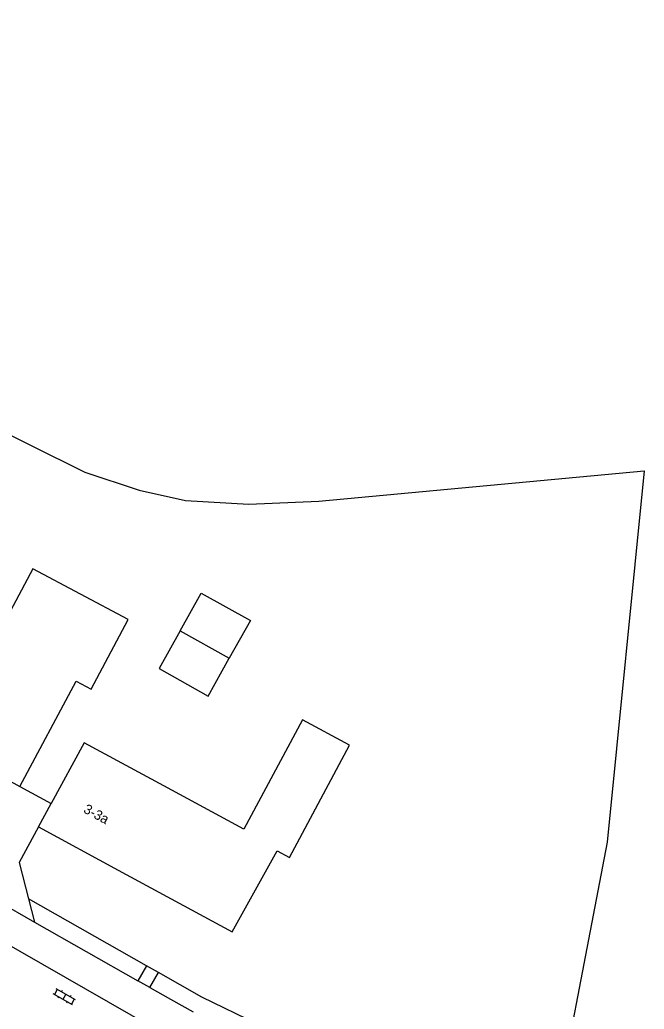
# Model space of a CAD drawing. Extents: x 132994 to 136000, y 393499 to 395512.
# Drawn here: x 133477.3 to 133541.2, y 393938.5 to 394039.8 of the extents above; entities that cross this region are included whole.
import ezdxf

# ---------------------------------------------------------------- set-up
doc = ezdxf.new("R2010")
doc.units = 0
for name, color, linetype in [('gg-anno-huisnummerreeks BGT', 7, 'Continuous'), ('gg-bbg-bijgebouw', 7, 'Continuous'), ('gg-bbg-gedigitaliseerde bijgebouw', 7, 'Continuous'), ('gg-bbg-hoofdgebouw', 7, 'Continuous'), ('gg-bbg-luifel en loopbrug', 7, 'Continuous'), ('gg-knt-verharding', 7, 'Continuous'), ('gt-grn-weggrens', 7, 'Continuous'), ('gt-symb-klinker verharding', 7, 'Continuous'), ('gx-grn-maaiveld', 7, 'Continuous')]:
    doc.layers.add(name, color=color, linetype=linetype)

# ---------------------------------------------------------------- blocks, each defined once
blk = doc.blocks.new('gt0-KL1')
at = {"layer": 'gt-symb-klinker verharding'}
for p, q in [((-1.15, 0.3), (1.15, 0.3)), ((-1, -0.3), (-1, 0.3)), ((-0.5, 0.3), (-0.5, 0.45)), ((0, -0.3), (0, 0.3)), ((0.5, 0.3), (0.5, 0.45)), ((1, -0.3), (1, 0.3)), ((-1.15, -0.3), (1.15, -0.3)), ((-0.5, -0.45), (-0.5, -0.3)), ((0.5, -0.45), (0.5, -0.3))]:
    blk.add_line(p, q, dxfattribs=at)

msp = doc.modelspace()

# ---------------------------------------------------------------- linework, layer by layer
at = {"layer": 'gg-bbg-bijgebouw'}
msp.add_line((133474.19, 393962.96), (133477.26, 393961.3), dxfattribs=at)
msp.add_lwpolyline([(133477.26, 393961.3), (133483.04, 393972.07), (133484.57, 393971.26), (133488.37, 393978.39), (133478.61, 393983.58), (133469.07, 393965.73), (133474.19, 393962.96)], dxfattribs=at)
at = {"layer": 'gg-bbg-gedigitaliseerde bijgebouw'}
msp.add_line((133493.69, 393977.23), (133498.71, 393974.42), dxfattribs=at)
msp.add_lwpolyline([(133493.69, 393977.23), (133495.85, 393981.1), (133500.88, 393978.28), (133498.71, 393974.42)], dxfattribs=at)
at = {"layer": 'gg-bbg-hoofdgebouw'}
for p, q in [((133479.17, 393957.14), (133480.48, 393959.56)), ((133479.17, 393957.14), (133487.34, 393952.71)), ((133487.34, 393952.71), (133499.01, 393946.39))]:
    msp.add_line(p, q, dxfattribs=at)
for points in [[(133499.01, 393946.39), (133503.61, 393954.7), (133504.87, 393954.01), (133511.04, 393965.52), (133506.21, 393968.12), (133500.2, 393956.91), (133492.02, 393961.34)], [(133492.02, 393961.34), (133483.84, 393965.77), (133480.48, 393959.56)]]:
    msp.add_lwpolyline(points, dxfattribs=at)
at = {"layer": 'gg-bbg-luifel en loopbrug'}
msp.add_lwpolyline([(133493.69, 393977.23), (133491.52, 393973.36), (133496.55, 393970.55), (133498.71, 393974.42)], dxfattribs=at)
at = {"layer": 'gg-knt-verharding'}
for p, q in [((133477.26, 393961.3), (133480.48, 393959.56)), ((133471.51, 393951.52), (133478.77, 393947.4))]:
    msp.add_line(p, q, dxfattribs=at)
at = {"layer": 'gt-grn-weggrens'}
msp.add_line((133490.97, 393936.52), (133474.01, 393946.26), dxfattribs=at)
at = {"layer": 'gx-grn-maaiveld'}
for p, q in [((133478.15, 393949.77), (133478.77, 393947.4)), ((133490.23, 393942.93), (133478.15, 393949.77)), ((133478.77, 393947.4), (133489.36, 393941.39)), ((133490.23, 393942.93), (133489.36, 393941.39)), ((133491.45, 393942.24), (133490.23, 393942.93)), ((133490.58, 393940.7), (133491.45, 393942.24)), ((133490.58, 393940.7), (133489.36, 393941.39))]:
    msp.add_line(p, q, dxfattribs=at)
for points in [[(133431.86, 394118.01), (133430.95, 394118.33), (133428.63, 394118.73), (133427.18, 394121.35), (133432.09, 394124.53), (133447.16, 394082.63), (133454.47, 394061.12), (133457.27, 394047.74), (133461.58, 394022.03), (133464.76, 394003.61), (133467.13, 394001.82), (133483.93, 393993.48), (133489.48, 393991.63), (133494.24, 393990.59), (133500.7, 393990.2), (133507.89, 393990.52), (133541.21, 393993.62), (133537.4, 393955.59), (133530.89, 393921.57)], [(133479.17, 393957.14), (133477.19, 393953.49), (133478.15, 393949.77)], [(133501.66, 393936.9), (133495.9, 393939.72), (133491.45, 393942.24)], [(133490.58, 393940.7), (133492.71, 393939.49), (133495.03, 393938.19)]]:
    msp.add_lwpolyline(points, dxfattribs=at)

# ---------------------------------------------------------------- block references
at = {"layer": 'gt-symb-klinker verharding', "rotation": 150.12717895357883}
msp.add_blockref('gt0-KL1', (133481.82, 393939.74), dxfattribs=at)

# ---------------------------------------------------------------- texts
at = {"layer": 'gg-anno-huisnummerreeks BGT'}
msp.add_text('3-3a', height=1, rotation=331.6, dxfattribs=at).set_placement((133483.7, 393958.67))

doc.saveas('drawing.dxf')
